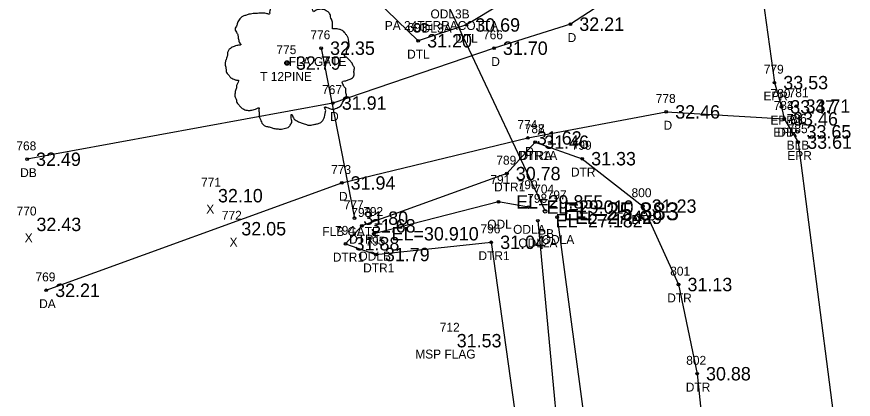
# Model space of a CAD drawing. Extents: x 2042117 to 2045853, y 303080 to 309569.
# Drawn here: x 2042751.6 to 2042845.4, y 307097.3 to 307140.2 of the extents above; entities that cross this region are included whole.
import ezdxf

# ---------------------------------------------------------------- set-up
doc = ezdxf.new("R2010")
doc.units = 0
for name, color, linetype in [('RD_DTM_BkLn_txCode', 7, 'Continuous'), ('RD_EX_DR_Pipe', 7, 'Continuous'), ('RD_EX_DR_Pipe_txCode', 7, 'Continuous'), ('RD_EX_Driveway', 7, 'Continuous'), ('RD_EX_Driveway_txCode', 7, 'Continuous'), ('RD_EX_Fence_Other', 7, 'Continuous'), ('RD_EX_Fence_Other_txCode', 7, 'Continuous'), ('RD_EX_H2O', 7, 'Continuous'), ('RD_EX_H2O_txCode', 7, 'Continuous'), ('RD_EX_Misc_txCode', 7, 'Continuous'), ('RD_EX_Road', 7, 'Continuous'), ('RD_EX_Road_txCode', 7, 'Continuous'), ('RD_EX_TX_Driveway_ELEV', 7, 'Continuous'), ('RD_EX_TX_Fence_Other_ELEV', 7, 'Continuous'), ('RD_EX_TX_H2O_ELEV', 7, 'Continuous'), ('RD_EX_TX_Misc_ELEV', 7, 'Continuous'), ('RD_EX_TX_Road_ELEV', 7, 'Continuous'), ('RD_EX_TX_VEG_ELEV', 7, 'Continuous'), ('RD_EX_VEG', 7, 'Continuous'), ('RD_EX_VEG_txCode', 7, 'Continuous'), ('RD_HC_Cl', 7, 'Continuous'), ('RD_SMD_Locator', 7, 'Continuous'), ('RD_TX_Pipe_ElevEX', 7, 'Continuous')]:
    doc.layers.add(name, color=color, linetype=linetype)

msp = doc.modelspace()

# ---------------------------------------------------------------- linework, layer by layer
at = {"layer": 'RD_EX_DR_Pipe'}
msp.add_line((2042799.852, 307141.729), (2042810.843, 307118.409), dxfattribs=at)
at = {"layer": 'RD_EX_Driveway'}
for points in [[(2042833.55, 307154.384), (2042825.159, 307146.837), (2042813.676, 307139.379), (2042805.118, 307136.689), (2042787.057, 307130.546), (2042752.791, 307124.242)], [(2042754.933, 307109.556), (2042788.047, 307121.589), (2042808.918, 307126.626), (2042824.427, 307129.552), (2042837.641, 307128.77)]]:
    msp.add_lwpolyline(points, dxfattribs=at)
at = {"layer": 'RD_EX_Fence_Other'}
msp.add_line((2042785.745, 307136.69), (2042789.469, 307117.644), dxfattribs=at)
at = {"layer": 'RD_EX_H2O'}
for points in [[(2042814.027, 307149.05), (2042810.112, 307144.206), (2042802.017, 307139.291), (2042796.625, 307137.517), (2042789.542, 307144.391), (2042765.069, 307170.219), (2042764.169, 307170.659), (2042753.465, 307183.772), (2042731.919, 307203.607), (2042715.016, 307220.147), (2042682.706, 307253.516), (2042652.804, 307280.333), (2042645.058, 307288.416)], [(2042809.741, 307126.164), (2042806.558, 307122.634), (2042790.31, 307116.781), (2042788.489, 307114.776), (2042791.888, 307113.566), (2042804.809, 307114.936), (2042810.254, 307075.927), (2042820.25, 307025.916), (2042830.402, 306977.214), (2042843.286, 306928.12), (2042852.907, 306878.242), (2042864.554, 306828.434), (2042879.232, 306781.717), (2042889.452, 306748.733), (2042886.162, 306741.984), (2042888.342, 306727.944), (2042896.131, 306676.354), (2042885.674, 306665.433), (2042857.251, 306612.72)], [(2042809.741, 307126.164), (2042815.006, 307124.307), (2042821.793, 307118.991), (2042825.803, 307110.204), (2042827.879, 307100.209), (2042830.079, 307078.706), (2042836.245, 307029.115), (2042845.477, 306980.043), (2042852.07, 306929.459), (2042864.584, 306881.255), (2042879.311, 306833.064), (2042893.367, 306784.782), (2042908.764, 306736.234), (2042928.775, 306689.39), (2042938.935, 306669.11)], [(2042808.991, 307118.887), (2042805.603, 307119.467), (2042791.641, 307115.891)], [(2042810.023, 307117.36), (2042813.866, 307076.179), (2042825.646, 307027.003), (2042835.988, 306978.447), (2042846.189, 306929.265), (2042857.498, 306879.973), (2042870.301, 306830.673), (2042885.373, 306782.676), (2042895.573, 306748.275), (2042892.025, 306740.631), (2042891.661, 306731.268), (2042905.953, 306680.583), (2042906.869, 306643.176), (2042864.966, 306605.633)], [(2042812.202, 307117.747), (2042817.664, 307076.987), (2042828.965, 307027.386), (2042840.42, 306978.95), (2042848.435, 306929.659), (2042859.837, 306880.358), (2042873.681, 306831.671), (2042888.543, 306783.43), (2042900.594, 306749.272), (2042902.903, 306733.666), (2042926.042, 306688.214), (2042936.455, 306668.372), (2042947.444, 306643.989), (2042966.182, 306597.912), (2042985.34, 306551.144), (2042987.611, 306538.586)]]:
    msp.add_lwpolyline(points, dxfattribs=at)
at = {"layer": 'RD_EX_Road'}
msp.add_lwpolyline([(2042828.357, 307428.87), (2042826.994, 307378.911), (2042826.878, 307329.287), (2042828.013, 307279.816), (2042830.497, 307230.241), (2042834.094, 307180.367), (2042835.887, 307157.733), (2042833.55, 307154.384), (2042836.54, 307132.831), (2042837.327, 307130.114), (2042837.641, 307128.77), (2042839.219, 307126.163), (2042844.982, 307081.334), (2042852.857, 307032.13), (2042861.739, 306982.988), (2042871.664, 306934.616), (2042883.382, 306885.882), (2042895.938, 306837.564), (2042909.761, 306789.886)], dxfattribs=at)
at = {"layer": 'RD_EX_VEG'}
for centre, radius in [((2042781.914, 307135.024), 0.25), ((2042781.901, 307135.005), 0.0001)]:
    msp.add_circle(centre, radius, dxfattribs=at)
for points in [[(2042782.045, 307142.191), (2042781.746, 307142.216), (2042781.421, 307142.116), (2042781.171, 307142.016), (2042780.946, 307141.941), (2042780.721, 307141.841), (2042780.421, 307141.666), (2042780.196, 307141.466), (2042780.071, 307141.216), (2042780.021, 307140.991), (2042779.971, 307140.716), (2042779.971, 307140.541), (2042779.846, 307140.516), (2042779.696, 307140.541), (2042779.447, 307140.616), (2042779.197, 307140.616), (2042778.947, 307140.616), (2042778.597, 307140.591), (2042778.247, 307140.591), (2042777.972, 307140.541), (2042777.647, 307140.492), (2042777.273, 307140.367), (2042776.923, 307140.242), (2042776.623, 307139.992), (2042776.373, 307139.517), (2042776.248, 307139.167), (2042776.098, 307138.917), (2042776.248, 307138.467), (2042776.423, 307138.118), (2042776.448, 307137.918), (2042776.523, 307137.493), (2042776.623, 307137.268), (2042776.748, 307137.068), (2042776.673, 307137.043), (2042776.298, 307136.993), (2042775.998, 307136.893), (2042775.573, 307136.668), (2042775.348, 307136.443), (2042775.248, 307136.118), (2042775.223, 307135.769), (2042775.124, 307135.569), (2042775.049, 307135.294), (2042775.024, 307135.219), (2042774.974, 307134.894), (2042775.074, 307134.444), (2042775.099, 307134.094), (2042775.223, 307133.869), (2042775.373, 307133.695), (2042775.548, 307133.445), (2042775.948, 307133.22), (2042776.273, 307133.12), (2042776.473, 307133.095), (2042776.298, 307132.595), (2042776.248, 307132.245), (2042776.123, 307131.845), (2042776.123, 307131.77), (2042776.073, 307131.296), (2042776.223, 307130.971), (2042776.298, 307130.596), (2042776.473, 307130.371), (2042776.748, 307130.071), (2042777.073, 307129.846), (2042777.572, 307129.721), (2042777.972, 307129.746), (2042778.547, 307129.921), (2042778.797, 307129.996), (2042778.772, 307129.821), (2042778.797, 307129.446), (2042778.797, 307129.022), (2042778.947, 307128.697), (2042779.047, 307128.422), (2042779.197, 307128.172), (2042779.522, 307127.947), (2042779.921, 307127.872), (2042780.346, 307127.722), (2042780.796, 307127.647), (2042781.296, 307127.622), (2042781.896, 307127.772), (2042782.17, 307127.897), (2042782.27, 307128.072), (2042782.47, 307128.447), (2042782.42, 307128.672), (2042782.445, 307129.271), (2042782.545, 307129.096), (2042782.72, 307128.747), (2042783.22, 307128.447), (2042783.62, 307128.272), (2042784.095, 307128.122), (2042784.394, 307128.047), (2042784.869, 307128.122), (2042785.244, 307128.197), (2042785.619, 307128.322), (2042785.919, 307128.597), (2042786.094, 307128.872), (2042786.144, 307129.146), (2042786.219, 307129.521), (2042786.269, 307129.696)], [(2042786.269, 307129.696), (2042786.194, 307129.871), (2042786.144, 307130.121), (2042786.219, 307130.096), (2042786.394, 307130.046), (2042786.668, 307129.921), (2042786.893, 307129.846), (2042787.218, 307129.871), (2042787.493, 307129.971), (2042787.943, 307130.246), (2042788.218, 307130.721), (2042788.493, 307131.121), (2042788.568, 307131.445), (2042788.518, 307131.67), (2042788.493, 307132.17), (2042788.293, 307132.42), (2042788.243, 307132.545), (2042788.143, 307132.945), (2042788.218, 307132.995), (2042788.493, 307133.045), (2042788.867, 307133.17), (2042789.142, 307133.295), (2042789.367, 307133.47), (2042789.442, 307133.695), (2042789.417, 307134.094), (2042789.467, 307134.494), (2042789.392, 307134.644), (2042789.292, 307134.794), (2042789.217, 307134.994), (2042789.067, 307135.144), (2042788.967, 307135.294), (2042788.867, 307135.394), (2042788.743, 307135.544), (2042788.568, 307135.669), (2042788.418, 307135.719), (2042788.368, 307135.869), (2042788.518, 307136.068), (2042788.568, 307136.168), (2042788.593, 307136.393), (2042788.818, 307136.743), (2042788.867, 307137.143), (2042788.818, 307137.568), (2042788.768, 307137.843), (2042788.618, 307138.118), (2042788.418, 307138.367), (2042788.293, 307138.542), (2042788.118, 307138.667), (2042787.793, 307138.792), (2042787.543, 307138.842), (2042787.193, 307138.842), (2042786.993, 307138.892), (2042787.018, 307138.942), (2042787.018, 307139.092), (2042787.018, 307139.367), (2042786.943, 307139.817), (2042786.793, 307140.317), (2042786.793, 307140.342), (2042786.693, 307140.591), (2042786.469, 307140.791), (2042786.294, 307140.891), (2042786.094, 307141.016), (2042785.844, 307141.041), (2042785.544, 307141.041), (2042785.269, 307140.991), (2042785.069, 307140.891), (2042784.894, 307140.766), (2042784.819, 307140.916), (2042784.719, 307141.216), (2042784.669, 307141.366), (2042784.519, 307141.541), (2042784.295, 307141.741), (2042783.845, 307141.866), (2042783.22, 307141.791), (2042782.92, 307141.591), (2042782.77, 307141.416), (2042782.72, 307141.541), (2042782.52, 307141.741), (2042782.42, 307141.916), (2042782.245, 307142.041), (2042782.095, 307142.141), (2042781.995, 307142.191)]]:
    msp.add_spline(points, degree=3, dxfattribs=at)
at = {"layer": 'RD_HC_Cl'}
msp.add_arc((2044751.247, 307348.431), 1911.291, 137.681845, 219.868361, dxfattribs=at)
at = {"layer": 'RD_SMD_Locator'}
for centre, radius in [((2042802.017, 307139.291), 0.15), ((2042813.676, 307139.379), 0.15), ((2042796.625, 307137.517), 0.15), ((2042785.745, 307136.69), 0.15), ((2042805.118, 307136.689), 0.15), ((2042781.914, 307135.024), 0.15), ((2042836.54, 307132.831), 0.15), ((2042787.057, 307130.546), 0.15), ((2042837.327, 307130.114), 0.15), ((2042839.035, 307130.2), 0.15), ((2042824.427, 307129.552), 0.15), ((2042837.641, 307128.77), 0.15), ((2042837.641, 307128.77), 0.15), ((2042839.142, 307127.322), 0.15), ((2042808.918, 307126.626), 0.15), ((2042809.741, 307126.164), 0.15), ((2042809.741, 307126.164), 0.15), ((2042839.219, 307126.163), 0.15), ((2042752.791, 307124.242), 0.15), ((2042815.006, 307124.307), 0.15), ((2042806.558, 307122.634), 0.15), ((2042788.047, 307121.589), 0.15), ((2042805.603, 307119.467), 0.15), ((2042808.991, 307118.887), 0.15), ((2042821.793, 307118.991), 0.15), ((2042810.843, 307118.409), 0.2), ((2042789.469, 307117.644), 0.15), ((2042810.023, 307117.36), 0.15), ((2042812.202, 307117.747), 0.15), ((2042790.31, 307116.781), 0.15), ((2042791.641, 307115.891), 0.15), ((2042788.489, 307114.776), 0.15), ((2042804.809, 307114.936), 0.15), ((2042791.888, 307113.566), 0.15), ((2042754.933, 307109.556), 0.15), ((2042825.803, 307110.204), 0.15), ((2042827.879, 307100.209), 0.15)]:
    msp.add_circle(centre, radius, dxfattribs=at)

# ---------------------------------------------------------------- texts
at = {"layer": 'RD_DTM_BkLn_txCode'}
for s, p in [('781', (2042838.137, 307131.2)), ('786', (2042837.938, 307128.322)), ('BL', (2042838.279, 307128.2)), ('BLB', (2042837.914, 307125.322))]:
    msp.add_text(s, height=1, dxfattribs=at).set_placement(p)
at = {"layer": 'RD_EX_DR_Pipe_txCode'}
for s, p in [('PA 24TERRACOTTA', (2042792.875, 307138.729)), ('704', (2042809.623, 307120.409)), ('PB', (2042810.064, 307115.409))]:
    msp.add_text(s, height=1, dxfattribs=at).set_placement(p)
at = {"layer": 'RD_EX_Driveway_txCode'}
for s, p in [('766', (2042803.89, 307137.689)), ('D', (2042813.369, 307137.379)), ('D', (2042804.811, 307134.689)), ('767', (2042785.852, 307131.546)), ('778', (2042823.246, 307130.552)), ('784', (2042836.46, 307129.77)), ('D', (2042786.75, 307128.546)), ('774', (2042807.736, 307127.626)), ('D', (2042824.12, 307127.552)), ('DB', (2042836.862, 307126.77)), ('768', (2042751.586, 307125.242)), ('D', (2042808.61, 307124.626)), ('773', (2042786.865, 307122.589)), ('DB', (2042752.011, 307122.242)), ('D', (2042787.74, 307119.589)), ('769', (2042753.729, 307110.556)), ('DA', (2042754.138, 307107.556))]:
    msp.add_text(s, height=1, dxfattribs=at).set_placement(p)
at = {"layer": 'RD_EX_Fence_Other_txCode'}
for s, p in [('776', (2042784.54, 307137.69)), ('FLA GATE', (2042782.119, 307134.69)), ('777', (2042788.287, 307118.644)), ('FLB GATE', (2042785.874, 307115.644))]:
    msp.add_text(s, height=1, dxfattribs=at).set_placement(p)
at = {"layer": 'RD_EX_H2O_txCode'}
for s, p in [('ODL3B', (2042797.998, 307140.026)), ('693', (2042795.42, 307138.517)), ('ODL3A', (2042795.981, 307138.437)), ('DTL', (2042800.773, 307137.291)), ('DTL', (2042795.381, 307135.517)), ('787', (2042808.56, 307127.164)), ('788', (2042808.56, 307127.164)), ('799', (2042813.825, 307125.307)), ('789', (2042805.377, 307123.634)), ('DTR1A', (2042807.82, 307124.164)), ('DTRA', (2042807.985, 307124.164)), ('DTR', (2042813.739, 307122.307)), ('791', (2042804.706, 307121.467)), ('790', (2042807.77, 307120.887)), ('DTR1', (2042805.125, 307120.634)), ('800', (2042820.533, 307119.991)), ('798', (2042808.842, 307119.36)), ('797', (2042811.02, 307119.747)), ('793', (2042789.128, 307117.781)), ('792', (2042790.46, 307117.891)), ('DTR', (2042820.525, 307116.991)), ('ODL', (2042804.359, 307116.467)), ('794', (2042787.308, 307115.776)), ('796', (2042803.604, 307115.936)), ('ODLA', (2042807.258, 307115.887)), ('DTR1', (2042788.876, 307114.781)), ('795', (2042790.707, 307114.566)), ('ODL2A', (2042807.842, 307114.36)), ('ODLA', (2042810.469, 307114.747)), ('DTR1', (2042787.056, 307112.776)), ('ODLB', (2042789.925, 307112.891)), ('DTR1', (2042803.376, 307112.936)), ('DTR1', (2042790.455, 307111.566)), ('801', (2042824.866, 307111.204)), ('DTR', (2042824.535, 307108.204)), ('802', (2042826.659, 307101.209)), ('DTR', (2042826.611, 307098.209))]:
    msp.add_text(s, height=1, dxfattribs=at).set_placement(p)
at = {"layer": 'RD_EX_Misc_txCode'}
for s, p in [('771', (2042772.284, 307121.161)), ('770', (2042751.615, 307117.942)), ('X', (2042772.867, 307118.161)), ('772', (2042774.615, 307117.46)), ('X', (2042752.52, 307114.942)), ('X', (2042775.481, 307114.46)), ('712', (2042799.04, 307104.913)), ('MSP FLAG', (2042796.292, 307101.913))]:
    msp.add_text(s, height=1, dxfattribs=at).set_placement(p)
at = {"layer": 'RD_EX_Road_txCode'}
for s, p in [('779', (2042835.359, 307133.831)), ('780', (2042836.107, 307131.114)), ('EPR', (2042835.312, 307130.831)), ('783', (2042836.46, 307129.77)), ('EPR', (2042836.099, 307128.114)), ('EPR', (2042836.413, 307126.77)), ('785', (2042838.038, 307127.163)), ('EPR', (2042837.991, 307124.163))]:
    msp.add_text(s, height=1, dxfattribs=at).set_placement(p)
at = {"layer": 'RD_EX_TX_Driveway_ELEV'}
for s, p in [('32.21', (2042814.676, 307138.629)), ('31.70', (2042806.118, 307135.939)), ('31.91', (2042788.057, 307129.796)), ('32.46', (2042825.427, 307128.802)), ('33.46', (2042838.641, 307128.02)), ('31.62', (2042809.918, 307125.876)), ('32.49', (2042753.791, 307123.492)), ('31.94', (2042789.047, 307120.839)), ('32.21', (2042755.933, 307108.806))]:
    msp.add_text(s, height=1.5, dxfattribs=at).set_placement(p)
at = {"layer": 'RD_EX_TX_Fence_Other_ELEV'}
for s, p in [('32.35', (2042786.745, 307135.94)), ('31.80', (2042790.469, 307116.894))]:
    msp.add_text(s, height=1.5, dxfattribs=at).set_placement(p)
at = {"layer": 'RD_EX_TX_H2O_ELEV'}
for s, p in [('30.69', (2042803.017, 307138.541)), ('31.20', (2042797.625, 307136.767)), ('31.46', (2042810.741, 307125.414)), ('31.46', (2042810.741, 307125.414)), ('31.33', (2042816.006, 307123.557)), ('30.78', (2042807.558, 307121.884)), ('EL=29.855', (2042807.603, 307118.717)), ('EL=29.010', (2042810.991, 307118.137)), ('31.23', (2042822.793, 307118.241)), ('EL=27.182', (2042812.023, 307116.61)), ('EL=27.429', (2042814.202, 307116.997)), ('31.68', (2042791.31, 307116.031)), ('EL=30.910', (2042793.641, 307115.141)), ('31.88', (2042789.489, 307114.026)), ('31.04', (2042805.809, 307114.186)), ('31.79', (2042792.888, 307112.816)), ('31.13', (2042826.803, 307109.454)), ('30.88', (2042828.879, 307099.459))]:
    msp.add_text(s, height=1.5, dxfattribs=at).set_placement(p)
at = {"layer": 'RD_EX_TX_Misc_ELEV'}
for s, p in [('33.71', (2042840.035, 307129.45)), ('33.65', (2042840.142, 307126.572)), ('32.10', (2042774.182, 307119.411)), ('32.43', (2042753.835, 307116.192)), ('32.05', (2042776.796, 307115.71)), ('31.53', (2042800.938, 307103.163))]:
    msp.add_text(s, height=1.5, dxfattribs=at).set_placement(p)
at = {"layer": 'RD_EX_TX_Road_ELEV'}
for s, p in [('33.53', (2042837.54, 307132.081)), ('33.47', (2042838.327, 307129.364)), ('33.46', (2042838.641, 307128.02)), ('33.61', (2042840.219, 307125.413))]:
    msp.add_text(s, height=1.5, dxfattribs=at).set_placement(p)
at = {"layer": 'RD_EX_TX_VEG_ELEV'}
msp.add_text('32.79', height=1.5, dxfattribs=at).set_placement((2042782.914, 307134.274))
at = {"layer": 'RD_EX_VEG_txCode'}
for s, p in [('775', (2042780.732, 307136.024)), ('T 12PINE', (2042778.91, 307133.024))]:
    msp.add_text(s, height=1, dxfattribs=at).set_placement(p)
at = {"layer": 'RD_TX_Pipe_ElevEX'}
msp.add_text('EL=25.883', height=2, dxfattribs=at).set_placement((2042812.843, 307117.409))

doc.saveas('drawing.dxf')
